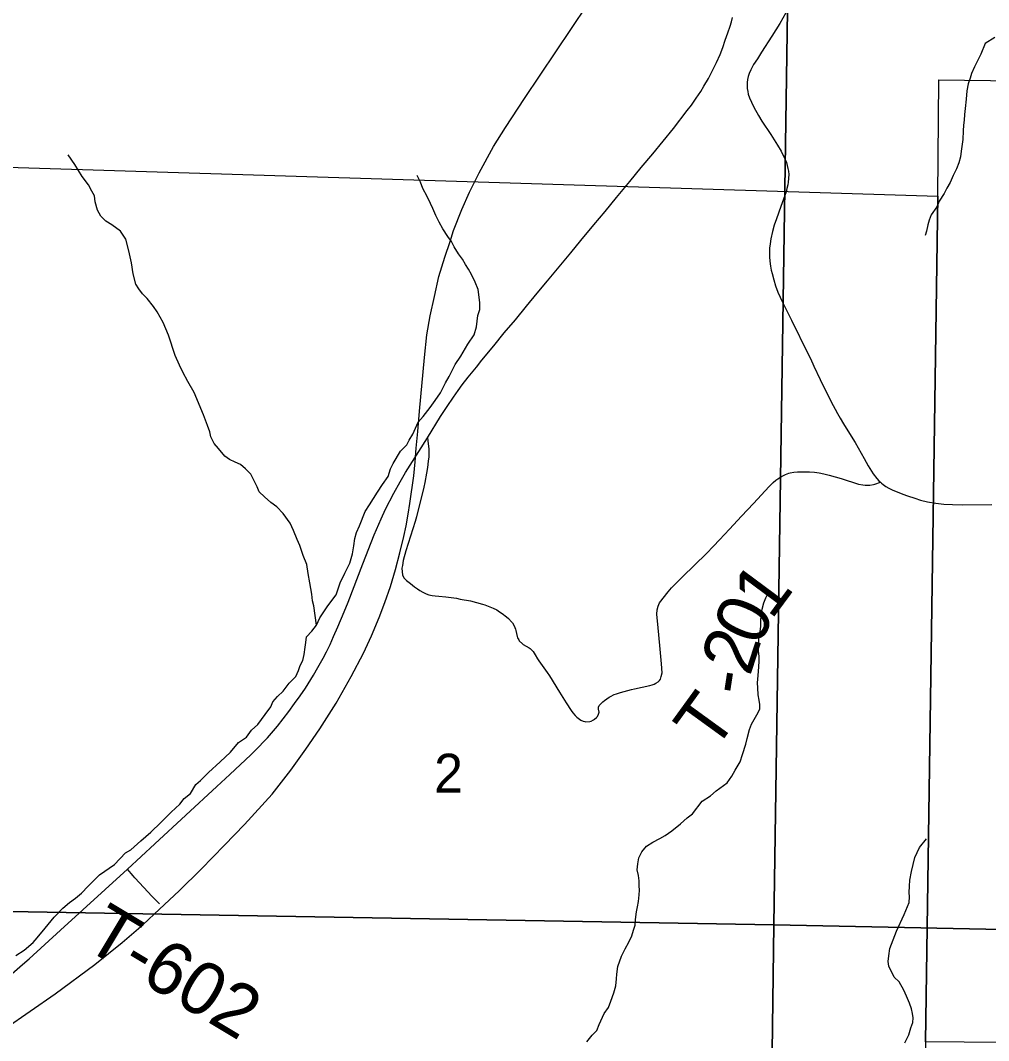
# Model space of a CAD drawing. Extents: x -19.9 to 41.9, y 0 to 32.3.
# Drawn here: x 3.184 to 4.229, y 15.736 to 16.837 of the extents above; entities that cross this region are included whole.
import ezdxf

# ---------------------------------------------------------------- set-up
doc = ezdxf.new("R2010")
doc.units = 0
for name, color, linetype in [('GM_X_Corporation', 7, 'Continuous'), ('GM_X_County_Road', 7, 'Continuous'), ('GM_X_Minor_River', 7, 'Continuous'), ('GM_X_Rail_Line', 7, 'Continuous'), ('GM_X_Section', 7, 'Continuous'), ('GM_X_Section_Text', 7, 'Continuous'), ('GM_X_State_Route', 7, 'Continuous'), ('GM_X_Township_Road', 7, 'Continuous'), ('GM_X_Township_Road_Text', 7, 'Continuous')]:
    doc.layers.add(name, color=color, linetype=linetype)

msp = doc.modelspace()

# ---------------------------------------------------------------- linework, layer by layer
at = {"layer": 'GM_X_Corporation'}
for points in [[(3.0015, 16.8981), (4.0122, 16.8721), (3.9969, 15.8607), (2.9854, 15.8784)], [(5.0159, 16.8409), (5.0026, 15.928), (5.0009, 15.8404), (3.9969, 15.8607), (4.0122, 16.8721)], [(2.9854, 15.8784), (3.9969, 15.8607), (3.9837, 14.8466), (2.9693, 14.8541)], [(3.9969, 15.8607), (5.0009, 15.8404), (4.9872, 14.9075), (4.9863, 14.8396), (3.9837, 14.8466)]]:
    msp.add_lwpolyline(points, close=True, dxfattribs=at)
at = {"layer": 'GM_X_County_Road'}
for points in [[(4.0101, 16.8452), (4.0034, 16.8338), (3.9949, 16.82), (3.9839, 16.8027), (3.9793, 16.7956), (3.9752, 16.7893), (3.9723, 16.7837), (3.9704, 16.7796), (3.9694, 16.7764), (3.9686, 16.7733), (3.9683, 16.7701), (3.9684, 16.7634), (3.9689, 16.7601), (3.9695, 16.7573), (3.9708, 16.7533), (3.9728, 16.7486), (3.9754, 16.7435), (3.9805, 16.7342), (3.9841, 16.7283), (3.9937, 16.7137), (4.001, 16.7023), (4.0048, 16.6958), (4.0076, 16.6905), (4.0094, 16.687), (4.0107, 16.6835), (4.0116, 16.6803), (4.0123, 16.6772), (4.0128, 16.6741), (4.0131, 16.6707), (4.0127, 16.6625), (4.0122, 16.6596), (4.0112, 16.6554), (4.0102, 16.6521), (4.0046, 16.6361), (3.9998, 16.6228), (3.9975, 16.6159), (3.9956, 16.6092), (3.9938, 16.6012), (3.993, 16.5958), (3.9925, 16.5912), (3.9923, 16.5864), (3.9924, 16.5817), (3.9928, 16.577), (3.9934, 16.5718), (3.9943, 16.5674), (3.9951, 16.5639), (3.997, 16.5568), (3.999, 16.5504), (4.0015, 16.5438), (4.0038, 16.5384), (4.0069, 16.5321), (4.0161, 16.5133), (4.0339, 16.4773)], [(4.0339, 16.4773), (4.0366, 16.4719), (4.0403, 16.4638), (4.047, 16.4495), (4.0551, 16.4331), (4.0611, 16.4215), (4.0632, 16.4173), (4.0656, 16.4128), (4.0688, 16.4075), (4.0724, 16.4016), (4.0789, 16.3911), (4.0849, 16.3813), (4.0946, 16.364), (4.0989, 16.3563), (4.1026, 16.3504), (4.1043, 16.3477), (4.1084, 16.3424), (4.1105, 16.3401), (4.112, 16.3386), (4.1131, 16.3376), (4.115, 16.336), (4.1179, 16.334), (4.1211, 16.3322), (4.1255, 16.3301), (4.1303, 16.328), (4.1362, 16.3257), (4.1413, 16.3238), (4.1491, 16.3213), (4.1554, 16.3193), (4.163, 16.3173), (4.1719, 16.3158), (4.1806, 16.3148), (4.1898, 16.3144), (4.2012, 16.3141), (4.2325, 16.3145)]]:
    msp.add_lwpolyline(points, dxfattribs=at)
at = {"layer": 'GM_X_Minor_River'}
for points in [[(4.2357, 16.8184), (4.2252, 16.8122), (4.2204, 16.8007), (4.2164, 16.7926), (4.2138, 16.7869), (4.2105, 16.7796), (4.209, 16.7746), (4.2069, 16.7685), (4.2055, 16.7609), (4.2045, 16.7521), (4.2035, 16.7418), (4.2028, 16.7353), (4.2025, 16.7292), (4.2018, 16.7239), (4.2015, 16.7178), (4.2009, 16.7086), (4.1999, 16.701), (4.1992, 16.6957), (4.1985, 16.6896), (4.1967, 16.6834), (4.1942, 16.6766)], [(3.5035, 16.1844), (3.5005, 16.2053), (3.4993, 16.2106), (3.4985, 16.2178), (3.4964, 16.23), (3.4944, 16.2402), (3.4931, 16.2497), (3.4892, 16.2596), (3.4856, 16.2702), (3.4825, 16.2766), (3.4785, 16.2864), (3.475, 16.2944), (3.4677, 16.3049), (3.4608, 16.312), (3.4543, 16.3165), (3.4473, 16.3229), (3.4416, 16.3281), (3.4396, 16.3334), (3.4361, 16.3402), (3.4326, 16.3474), (3.4268, 16.353), (3.4215, 16.3575), (3.4158, 16.3601), (3.4097, 16.363), (3.4047, 16.3668), (3.3977, 16.375), (3.3931, 16.3803), (3.3896, 16.3875), (3.3884, 16.3931), (3.386, 16.3996), (3.3817, 16.4113), (3.3715, 16.4355), (3.3645, 16.4472), (3.3594, 16.4574), (3.3555, 16.465), (3.3509, 16.4752), (3.3437, 16.4971), (3.3382, 16.5108), (3.3316, 16.5225), (3.3277, 16.5281), (3.3208, 16.5368), (3.3158, 16.542), (3.3116, 16.5473), (3.3085, 16.5522), (3.3056, 16.5636), (3.304, 16.5753), (3.3011, 16.5882), (3.2979, 16.6008), (3.2921, 16.6094), (3.2825, 16.6165), (3.276, 16.6202), (3.2707, 16.6258), (3.2672, 16.6323), (3.2648, 16.641), (3.2639, 16.6478), (3.2612, 16.6527), (3.2573, 16.6595), (3.2507, 16.6686), (3.2426, 16.6814), (3.2356, 16.6919)], [(4.1942, 16.6766), (4.1905, 16.6696), (4.1872, 16.662), (4.1839, 16.6558), (4.1809, 16.6501), (4.1754, 16.642), (4.1728, 16.6359), (4.1669, 16.627), (4.1647, 16.6213), (4.1633, 16.6163), (4.1618, 16.6094), (4.1604, 16.605)], [(3.4108, 16.0471), (3.4194, 16.0575), (3.428, 16.0634), (3.4332, 16.071), (3.4403, 16.0769), (3.444, 16.0823), (3.4481, 16.088), (3.4541, 16.0961), (3.4562, 16.1015), (3.4615, 16.1073), (3.4674, 16.1131), (3.4741, 16.1215), (3.4812, 16.1289), (3.4841, 16.1354), (3.486, 16.1408), (3.4889, 16.1461), (3.4903, 16.1526), (3.4914, 16.1606), (3.492, 16.1656), (3.4927, 16.1717), (3.4983, 16.1779), (3.5035, 16.1844), (3.5072, 16.1921), (3.5157, 16.2052), (3.5246, 16.2171), (3.529, 16.2301), (3.5341, 16.2405), (3.5393, 16.2512), (3.5425, 16.2611), (3.5439, 16.2699), (3.5449, 16.2779), (3.5467, 16.2841), (3.55, 16.2913), (3.5559, 16.307), (3.5607, 16.314), (3.5692, 16.3278), (3.5748, 16.3359), (3.5807, 16.3447), (3.5832, 16.3531), (3.5862, 16.3589), (3.5943, 16.372), (3.601, 16.3789), (3.6036, 16.3839), (3.6073, 16.3904), (3.6131, 16.4035), (3.6187, 16.4096), (3.6262, 16.4193), (3.6314, 16.4266), (3.6373, 16.435), (3.6428, 16.4458), (3.6465, 16.4527), (3.6531, 16.4657), (3.6594, 16.4746), (3.6668, 16.4876), (3.6735, 16.4976), (3.676, 16.5064), (3.6777, 16.5183), (3.6799, 16.5248), (3.6798, 16.5324), (3.6781, 16.5464), (3.6749, 16.5544), (3.6707, 16.5627), (3.6676, 16.5684), (3.6644, 16.5736), (3.661, 16.5793), (3.6567, 16.5849), (3.6521, 16.5925), (3.6493, 16.5982), (3.6451, 16.6038), (3.64, 16.6121), (3.6358, 16.6193), (3.6323, 16.6264), (3.6291, 16.634), (3.6264, 16.6393), (3.6229, 16.6469), (3.6182, 16.6555), (3.6158, 16.6624), (3.6123, 16.6695)], [(3.9808, 16.1689), (3.9822, 16.1773), (3.9829, 16.183), (3.9832, 16.1884), (3.9835, 16.1948), (3.9841, 16.2002), (3.9863, 16.2082), (3.9885, 16.2136), (3.9897, 16.2167)], [(3.7952, 15.7344), (3.8011, 15.7417), (3.806, 15.7468), (3.8085, 15.7533), (3.814, 15.7652), (3.8185, 15.7717), (3.821, 15.7786), (3.8243, 15.7874), (3.8265, 15.795), (3.8271, 15.8027), (3.8278, 15.8076), (3.8288, 15.816), (3.8328, 15.8271), (3.8365, 15.8348), (3.8405, 15.8421), (3.8439, 15.849), (3.8457, 15.8551), (3.8475, 15.8604), (3.8478, 15.8665), (3.8488, 15.8749), (3.8498, 15.8803), (3.8509, 15.886), (3.8519, 15.8933), (3.8522, 15.8982), (3.8518, 15.9031), (3.8517, 15.9085), (3.8509, 15.9142), (3.8496, 15.9202), (3.8503, 15.9267), (3.8513, 15.9332), (3.8546, 15.9397), (3.8595, 15.9459), (3.8666, 15.9502), (3.8741, 15.9541), (3.8798, 15.9572), (3.8869, 15.9623), (3.8962, 15.9697), (3.9037, 15.9763), (3.9093, 15.9805), (3.9197, 15.9944), (3.9287, 15.9999), (3.9347, 16.0053), (3.9467, 16.0142), (3.9519, 16.0212), (3.9552, 16.0277), (3.9608, 16.0369), (3.9633, 16.0445), (3.9669, 16.056), (3.9684, 16.0621), (3.9709, 16.0717), (3.973, 16.0774), (3.9786, 16.0874), (3.9819, 16.0936), (3.9818, 16.0985), (3.9814, 16.1034), (3.9802, 16.1091), (3.9797, 16.1167), (3.9796, 16.1221), (3.9802, 16.1301), (3.9809, 16.1392), (3.9811, 16.1453), (3.9811, 16.1506), (3.9806, 16.1567), (3.9808, 16.1689)], [(3.1789, 15.8277), (3.1879, 15.8336), (3.1976, 15.8417), (3.2021, 15.8467), (3.2107, 15.8571), (3.2203, 15.8691), (3.2297, 15.8787), (3.2371, 15.885), (3.2435, 15.8896), (3.2499, 15.895), (3.257, 15.9024), (3.2693, 15.9148), (3.2854, 15.926), (3.2973, 15.9384), (3.303, 15.9419), (3.3138, 15.9516), (3.3246, 15.9609), (3.3355, 15.9713), (3.3467, 15.9826), (3.356, 15.9911), (3.3608, 15.9972), (3.3676, 16.0027), (3.3731, 16.0123), (3.3784, 16.0165), (3.3869, 16.0254), (3.3996, 16.0367), (3.4108, 16.0471)], [(4.1435, 15.8909), (4.143, 15.8958), (4.1433, 15.9027), (4.144, 15.9091), (4.1458, 15.9183), (4.1493, 15.9336), (4.1541, 15.9443), (4.1619, 15.9536)], [(4.1386, 15.7336), (4.1426, 15.742), (4.1448, 15.7497), (4.147, 15.7554), (4.1473, 15.7604), (4.1468, 15.7653), (4.1456, 15.7702), (4.1433, 15.7763), (4.1401, 15.7839), (4.1374, 15.7903), (4.1323, 15.7993), (4.127, 15.8042), (4.1211, 15.8163), (4.1203, 15.8212), (4.1213, 15.8273), (4.1223, 15.8354), (4.1296, 15.8541), (4.1377, 15.8721), (4.1432, 15.8848), (4.1435, 15.8909)]]:
    msp.add_lwpolyline(points, dxfattribs=at)
at = {"layer": 'GM_X_Rail_Line'}
msp.add_lwpolyline([(3.1676, 15.7489), (3.2214, 15.7865), (3.2641, 15.8182), (3.2936, 15.8418), (3.3164, 15.8613), (3.3342, 15.8777), (3.3553, 15.8975), (3.379, 15.921), (3.4042, 15.9467), (3.4258, 15.969), (3.4555, 16.002), (3.4757, 16.0279), (3.4921, 16.0504), (3.5071, 16.0723), (3.5247, 16.1), (3.541, 16.1289), (3.5541, 16.1541), (3.563, 16.1729), (3.5711, 16.1927), (3.5773, 16.2089), (3.5834, 16.2259), (3.5886, 16.2443), (3.5936, 16.2624), (3.5978, 16.2798), (3.6002, 16.2915), (3.6024, 16.3039), (3.6042, 16.3156), (3.6084, 16.3455), (3.6099, 16.3604), (3.6111, 16.3752), (3.6128, 16.3933), (3.6145, 16.4154), (3.6199, 16.4733), (3.6227, 16.4976), (3.6263, 16.5181), (3.6307, 16.5391), (3.6356, 16.5604), (3.6419, 16.5816), (3.6476, 16.5984), (3.6515, 16.6101), (3.6605, 16.6329), (3.6688, 16.6517), (3.6789, 16.6725), (3.6947, 16.7008), (3.7076, 16.7213), (3.7281, 16.7526), (3.7957, 16.8533)], dxfattribs=at)
at = {"layer": 'GM_X_Section'}
for points in [[(4.1751, 16.7729), (5.0099, 16.7619), (4.9984, 15.7274), (4.1607, 15.7345), (4.1739, 16.6474)], [(4.1739, 16.6474), (4.1607, 15.7345), (4.1589, 15.6469), (3.155, 15.6672), (3.1702, 16.6786)]]:
    msp.add_lwpolyline(points, close=True, dxfattribs=at)
at = {"layer": 'GM_X_State_Route'}
msp.add_lwpolyline([(3.1717, 15.8055), (3.1862, 15.8182), (3.1933, 15.8243), (3.2272, 15.8549), (3.2996, 15.921), (3.329, 15.9484), (3.3959, 16.01), (3.4099, 16.0231), (3.4327, 16.0444), (3.4369, 16.0485), (3.4506, 16.0628), (3.455, 16.0677), (3.4614, 16.0753), (3.4675, 16.0832), (3.4736, 16.0912), (3.4799, 16.0996), (3.486, 16.108), (3.4916, 16.1164), (3.5001, 16.1302), (3.5049, 16.1384), (3.5108, 16.1488), (3.5143, 16.1555), (3.5181, 16.1635), (3.522, 16.172), (3.5267, 16.1826), (3.5335, 16.1985), (3.5376, 16.209), (3.5535, 16.2503), (3.5657, 16.2817), (3.5733, 16.299), (3.578, 16.3094), (3.587, 16.3269), (3.5937, 16.339), (3.5997, 16.3489), (3.6046, 16.3569), (3.6232, 16.3865), (3.6374, 16.4095), (3.6446, 16.4202), (3.6514, 16.4304), (3.6564, 16.4377), (3.6608, 16.4437), (3.6672, 16.452), (3.676, 16.4626), (3.6821, 16.4701), (3.6948, 16.4859), (3.706, 16.4996), (3.7181, 16.5139), (3.7303, 16.5287), (3.7418, 16.5425), (3.7529, 16.5559), (3.7655, 16.5709), (3.778, 16.5862), (3.7889, 16.5994), (3.8029, 16.6164), (3.815, 16.6307), (3.8274, 16.646), (3.8415, 16.6631), (3.854, 16.6781), (3.8664, 16.693), (3.8778, 16.7067), (3.8889, 16.7203), (3.9037, 16.7396), (3.9083, 16.7456), (3.9132, 16.7529), (3.9181, 16.7602), (3.9216, 16.7659), (3.9264, 16.7741), (3.9314, 16.7837), (3.9352, 16.7917), (3.939, 16.8003), (3.942, 16.8079), (3.9447, 16.8156), (3.9474, 16.8235), (3.9498, 16.8306), (3.9513, 16.8354), (3.9526, 16.8402)], dxfattribs=at)
at = {"layer": 'GM_X_Township_Road'}
for points in [[(3.6232, 16.3865), (3.6241, 16.38), (3.6246, 16.3747), (3.6248, 16.3699), (3.6246, 16.3659), (3.6241, 16.3611), (3.6232, 16.3546), (3.6223, 16.3484), (3.6204, 16.3384), (3.6193, 16.3332), (3.6114, 16.3013), (3.61, 16.296), (3.5998, 16.2645), (3.5971, 16.2542), (3.5962, 16.2488), (3.5957, 16.2456), (3.5964, 16.2383), (3.5982, 16.2351), (3.6007, 16.2326)], [(3.6007, 16.2326), (3.605, 16.2291), (3.6094, 16.2255), (3.6124, 16.2233), (3.6149, 16.2217), (3.6184, 16.2198), (3.6218, 16.2181), (3.6246, 16.217), (3.6282, 16.2163), (3.6314, 16.2158), (3.6354, 16.2155), (3.6431, 16.2147), (3.6545, 16.2133), (3.6587, 16.2125), (3.6698, 16.2104), (3.6825, 16.207), (3.685, 16.2062), (3.6905, 16.2042), (3.694, 16.2027), (3.698, 16.2007), (3.7011, 16.1988), (3.7038, 16.197), (3.7085, 16.1932), (3.7107, 16.1913), (3.714, 16.1878), (3.7149, 16.1867), (3.7163, 16.1842), (3.7176, 16.1819), (3.7183, 16.1798), (3.7187, 16.1786), (3.72, 16.1721), (3.7205, 16.1706), (3.7217, 16.1684), (3.7223, 16.1675), (3.7259, 16.1642), (3.7267, 16.1635), (3.7329, 16.1597), (3.734, 16.1591), (3.7363, 16.157), (3.7372, 16.1559), (3.7396, 16.1522), (3.7421, 16.1481), (3.7435, 16.1458), (3.7523, 16.1333), (3.7548, 16.1295), (3.7658, 16.112), (3.7731, 16.1005), (3.7784, 16.0921), (3.7803, 16.0895), (3.7827, 16.0866), (3.7845, 16.0848), (3.7872, 16.0827), (3.7886, 16.0819), (3.7914, 16.0807), (3.793, 16.0802), (3.7943, 16.08), (3.7984, 16.0803), (3.7998, 16.0808), (3.8025, 16.0821), (3.8037, 16.0828), (3.8057, 16.0845), (3.8066, 16.0857), (3.8079, 16.0882), (3.8083, 16.0893), (3.8084, 16.0903), (3.8079, 16.0935), (3.8078, 16.0949), (3.808, 16.0959), (3.8086, 16.0974), (3.8093, 16.0984), (3.8126, 16.1016), (3.8142, 16.1029), (3.8194, 16.1065), (3.8208, 16.1074), (3.8246, 16.1093), (3.8271, 16.1102), (3.8315, 16.1117), (3.8433, 16.1148), (3.8467, 16.1156), (3.8633, 16.119), (3.8659, 16.1197), (3.8678, 16.1206), (3.8698, 16.1217), (3.8722, 16.1231), (3.8737, 16.1246), (3.8747, 16.1259), (3.8756, 16.1287), (3.8765, 16.1328), (3.876, 16.1424), (3.874, 16.1622), (3.8722, 16.1813), (3.8708, 16.1963), (3.871, 16.2008), (3.8722, 16.2047), (3.8735, 16.2083), (3.8832, 16.2202), (3.8868, 16.2244), (3.8927, 16.2306), (3.8984, 16.2363), (3.9116, 16.2491), (3.9245, 16.2617), (3.9321, 16.2694), (3.9385, 16.2762), (3.9492, 16.2878), (3.9623, 16.3019), (3.9685, 16.3086), (3.975, 16.3156), (3.9922, 16.3338), (3.9964, 16.3381), (3.9994, 16.3409), (4.0014, 16.3423), (4.0054, 16.3447), (4.0096, 16.3468), (4.0131, 16.3482), (4.0147, 16.3487), (4.0186, 16.3493), (4.0225, 16.3497), (4.0304, 16.3499), (4.0356, 16.3497), (4.0411, 16.3493), (4.0459, 16.3487), (4.051, 16.3475), (4.0567, 16.3461), (4.0699, 16.3424), (4.0753, 16.3407), (4.0829, 16.3383), (4.0886, 16.3366), (4.093, 16.3356), (4.0958, 16.3353), (4.1008, 16.3354), (4.1046, 16.336), (4.1059, 16.3363), (4.112, 16.3386)], [(3.3339, 15.8836), (3.3259, 15.8919), (3.317, 15.9013), (3.3074, 15.9117), (3.3057, 15.9137), (3.2996, 15.921)]]:
    msp.add_lwpolyline(points, dxfattribs=at)

# ---------------------------------------------------------------- texts
at = {"layer": 'GM_X_Section_Text'}
msp.add_text('2', height=0.0419, rotation=0, dxfattribs=at).set_placement((3.6304, 16.0036))
at = {"layer": 'GM_X_Township_Road_Text'}
for s, height, rotation, p in [('1', 0.0568, 53.4351, (3.9942, 16.189)), ('0', 0.0568, 65.6069, (3.9813, 16.1599)), ('2', 0.0568, 72.067, (3.9712, 16.1282)), ('-', 0.0568, 81.1849, (3.9681, 16.1074)), ('T', 0.0568, 54.0533, (3.9321, 16.0462)), ('T-602', 0.05682, 329.0364, (3.2503, 15.8374))]:
    msp.add_text(s, height=height, rotation=rotation, dxfattribs=at).set_placement(p)

doc.saveas('drawing.dxf')
